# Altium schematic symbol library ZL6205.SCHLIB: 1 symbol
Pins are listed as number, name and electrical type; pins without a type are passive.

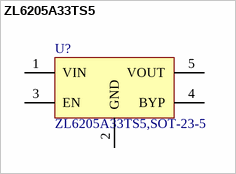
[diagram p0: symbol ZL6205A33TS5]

## ZL6205A33TS5
designator U?, comment ZL6205A33TS5,SOT-23-5
ZL6205A33TS5,SOT-23-5,ZLG; 物料代码: 08.09.03069; 名称: 集成电路; 贴片和直插: SMT; PCB备注: 190806hcj; 器件优选方案: 待导入物料
footprint SOT-23-5
pins: 1 VIN, 2 GND, 3 EN, 4 BYP, 5 VOUT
